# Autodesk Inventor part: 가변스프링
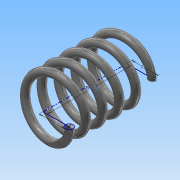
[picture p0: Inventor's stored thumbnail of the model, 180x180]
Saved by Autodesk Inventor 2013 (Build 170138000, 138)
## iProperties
Created: 2019-10
Part Number: 가변스프링
Material: 스테인리스강
Document SubType Name: Modeling
Designer: Administrator
Density: 8.08 g/cm^3
Mass: 147.867 g
Surface Area: 124.153 cm^2
Volume: 18.3003 cm^3
Author: Administrator
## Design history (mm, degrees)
sketch "스케치1"
  geometry: L1 (0, 0)-(0, 67.25); L2 (0, 0)-(21, 0); L3 (0, 67.25)-(21, 67.25); C1 r 3 at (21, 0)
  constraints: 6 end point, 1 centre point, 1 coincident, 1 parallel, 1 perpendicular, 1 vertical
  dimensions: "d0" = 21 distance of L1.start L2.end; "d1" = 67.25 distance of L1.start L1.end (derived); "d2" = 21 distance of L1.end L3.end; "d3" = 6 diameter of C1
feature "코일1" sketch "스케치1" pitch "d4" = 10; turns "d6" = 5; dims "d5" = 67.25 (= d1), "d7" = 0, angle "d8" = 90 deg, angle "d9" = 90 deg, "d10" = 0, "d11" = 0
sketch "스케치2"
  geometry: L1 (-25, 67.25)-(25, 67.25); L2 (25, 67.25)-(25, 0); L3 (25, 0)-(-25, 0); L4 (-25, 0)-(-25, 67.25); 2 further points
  constraints: 8 end point, 2 parallel, 1 coincident, 1 horizontal, 1 midpoint, 1 perpendicular
  dimensions: "d12" = 50 distance of L2.end L3.end; "d14" = 67.25 distance of L3.end L1.start (= d1)
extrude "돌출1" sketch "스케치2" stored distance "d15" = 50; taper "d16" = 0 deg
node "솔리드1"
